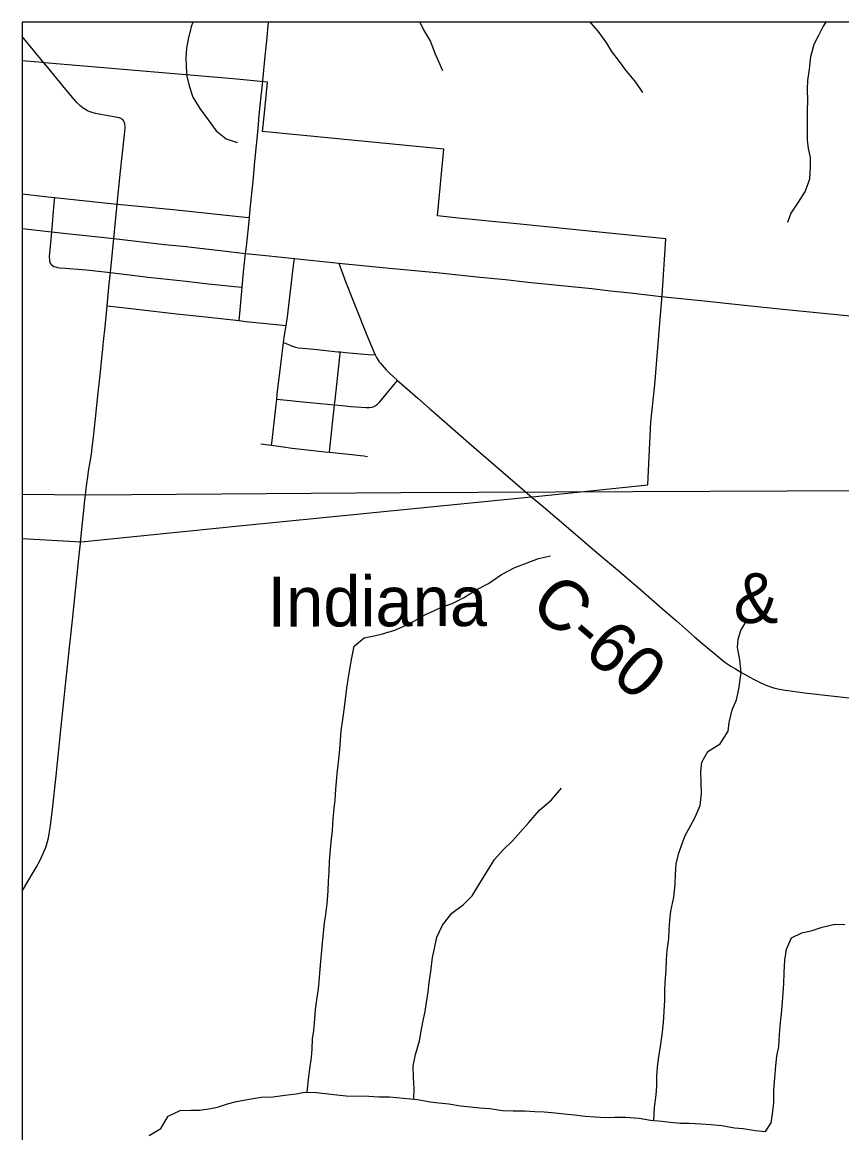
# Model space of a CAD drawing. Extents: x 0 to 1052, y -194 to 246.
# Drawn here: x 1.982 to 2.91, y 19.749 to 21.005 of the extents above; entities that cross this region are included whole.
import ezdxf

# ---------------------------------------------------------------- set-up
doc = ezdxf.new("R2010")
doc.units = 0
for name, color, linetype in [('GM_X_City_Street', 7, 'Continuous'), ('GM_X_Corporation', 7, 'Continuous'), ('GM_X_County_Road', 7, 'Continuous'), ('GM_X_County_Road_Text', 7, 'Continuous'), ('GM_X_Minor_River', 7, 'Continuous'), ('GM_X_Rail_Line', 7, 'Continuous'), ('GM_X_Rail_Line_Text', 7, 'Continuous'), ('GM_X_State_Route', 7, 'Continuous'), ('GM_X_Township_Road', 7, 'Continuous')]:
    doc.layers.add(name, color=color, linetype=linetype)

msp = doc.modelspace()

# ---------------------------------------------------------------- linework, layer by layer
at = {"layer": 'GM_X_City_Street'}
for points in [[(1.9822, 20.8114), (2.008, 20.8085), (2.0186, 20.8073), (2.0437, 20.8045), (2.0897, 20.7995), (2.1022, 20.7984), (2.1529, 20.7936), (2.164, 20.7925), (2.1991, 20.7888), (2.2343, 20.7851), (2.2393, 20.7846)], [(2.0186, 20.8073), (2.018, 20.8008), (2.0152, 20.7685), (2.013, 20.744), (2.0128, 20.7414), (2.0127, 20.7392), (2.0129, 20.7371), (2.0131, 20.7353), (2.0139, 20.7329), (2.0149, 20.7314), (2.0163, 20.7302), (2.0179, 20.7293), (2.0203, 20.7286), (2.0222, 20.7282), (2.0246, 20.7278), (2.0308, 20.7273), (2.05, 20.7259), (2.0549, 20.7253), (2.0753, 20.7232), (2.0819, 20.7223), (2.0851, 20.7219), (2.1097, 20.7188), (2.1245, 20.7171), (2.1678, 20.7124), (2.1801, 20.7109), (2.1893, 20.7098), (2.2004, 20.7087), (2.2224, 20.7065), (2.2312, 20.7057)], [(2.2276, 20.668), (2.2284, 20.6761), (2.2308, 20.7011), (2.2312, 20.7057), (2.2327, 20.7227), (2.2349, 20.744)], [(2.2644, 20.5269), (2.265, 20.5324), (2.2692, 20.5694), (2.2701, 20.5792), (2.2707, 20.5848), (2.275, 20.6212), (2.2779, 20.6431), (2.279, 20.6513), (2.2807, 20.6625), (2.2822, 20.6723), (2.2892, 20.7302), (2.2902, 20.7382)], [(2.0783, 20.6845), (2.0985, 20.6823), (2.131, 20.6787), (2.1569, 20.6758), (2.1791, 20.6734), (2.2069, 20.6705), (2.2276, 20.668), (2.2353, 20.6671), (2.2656, 20.664), (2.2807, 20.6625)], [(2.2779, 20.6431), (2.2853, 20.64), (2.287, 20.6393), (2.2893, 20.6386), (2.2915, 20.6379), (2.2949, 20.6373), (2.2998, 20.6368), (2.3159, 20.6352), (2.3394, 20.6327), (2.3423, 20.6325), (2.3481, 20.632), (2.3736, 20.6298), (2.3817, 20.6291)], [(2.3299, 20.519), (2.3307, 20.5267), (2.3355, 20.5728), (2.3361, 20.578), (2.3417, 20.6275), (2.3423, 20.6325)], [(2.2701, 20.5792), (2.3039, 20.5758), (2.3355, 20.5728), (2.3442, 20.5719), (2.3541, 20.5708), (2.3715, 20.5696), (2.3732, 20.5696), (2.3752, 20.5697), (2.3777, 20.5701), (2.3794, 20.5706), (2.3806, 20.5711), (2.3817, 20.5717), (2.3828, 20.5724), (2.3842, 20.5735), (2.3868, 20.5762), (2.4032, 20.5957), (2.4069, 20.6002)], [(2.2521, 20.5286), (2.2607, 20.5274), (2.2644, 20.5269), (2.2773, 20.525), (2.2876, 20.5237), (2.3013, 20.522), (2.3247, 20.5196), (2.3299, 20.519), (2.355, 20.5164), (2.3648, 20.5153), (2.3688, 20.5149), (2.3728, 20.5141)]]:
    msp.add_lwpolyline(points, dxfattribs=at)
at = {"layer": 'GM_X_Corporation'}
for points in [[(5.1788, 17.6981), (5.491, 17.9457), (6.1888, 18.4644), (6.5994, 18.7694), (6.8785, 18.9763), (8.1871, 19.9814), (8.6571, 20.341), (8.7822, 20.435), (8.7822, 21.0055), (1.9822, 21.0055), (1.9822, 14.2055)], [(5.1788, 17.6981), (5.491, 17.9457), (6.1888, 18.4644), (6.152, 18.6129), (5.992, 19.3448), (5.9283, 19.6076), (5.6935, 20.5776), (5.5898, 21.0055), (1.9822, 21.0055), (1.9822, 14.2055)]]:
    msp.add_lwpolyline(points, dxfattribs=at)
msp.add_lwpolyline([(1.9822, 20.9617), (1.9822, 20.4216), (2.0488, 20.4178), (2.2277, 20.4357), (2.372, 20.45), (2.5543, 20.4682), (2.5596, 20.4685), (2.6902, 20.4821), (2.6935, 20.5535), (2.6981, 20.5952), (2.7035, 20.6649), (2.7061, 20.6962), (2.7103, 20.7605), (2.6198, 20.7695), (2.5793, 20.7736), (2.5343, 20.7781), (2.5135, 20.7802), (2.4988, 20.7816), (2.4758, 20.7839), (2.452, 20.7863), (2.4593, 20.862), (2.2542, 20.8818), (2.2562, 20.9024), (2.2597, 20.9377), (2.2208, 20.9415), (2.0074, 20.9596), (2.0006, 20.9602)], close=True, dxfattribs=at)
at = {"layer": 'GM_X_County_Road'}
for p, q in [((2.0819, 20.7223), (2.0858, 20.7608)), ((2.5593, 20.4679), (2.5693, 20.4594))]:
    msp.add_line(p, q, dxfattribs=at)
for points in [[(2.254, 20.935), (2.2568, 20.9634), (2.2589, 20.9844), (2.261, 21.0055)], [(2.2491, 20.885), (2.2504, 20.9003), (2.2519, 20.9152), (2.254, 20.935)], [(2.2393, 20.7846), (2.2402, 20.794), (2.2433, 20.8256), (2.2455, 20.8479), (2.2491, 20.885)], [(2.2349, 20.744), (2.2358, 20.7519), (2.2382, 20.773), (2.2393, 20.7846)], [(2.3403, 20.7329), (2.3479, 20.7123), (2.3565, 20.6903), (2.3588, 20.6845), (2.3713, 20.6534), (2.3799, 20.6327), (2.3817, 20.6291)], [(2.0783, 20.6845), (2.0806, 20.7097), (2.0819, 20.7223)], [(2.0481, 20.4163), (2.0482, 20.4173), (2.0521, 20.4568), (2.0527, 20.462), (2.0537, 20.4704), (2.0543, 20.4747), (2.055, 20.4807), (2.0557, 20.4863), (2.0563, 20.4908), (2.0573, 20.4977), (2.0587, 20.5061), (2.0604, 20.517), (2.0609, 20.5202), (2.0614, 20.5243), (2.0628, 20.5362), (2.065, 20.5571), (2.0681, 20.5866), (2.0703, 20.6061), (2.0717, 20.6213), (2.0726, 20.6294), (2.0733, 20.6355), (2.0738, 20.6404), (2.0742, 20.6445), (2.076, 20.6609), (2.0775, 20.6764), (2.0783, 20.6845)], [(2.3817, 20.6291), (2.3829, 20.6264), (2.385, 20.6233), (2.3862, 20.6214), (2.3876, 20.6197), (2.3893, 20.6175), (2.3916, 20.6149), (2.3939, 20.6123), (2.3972, 20.609), (2.4018, 20.6048), (2.4069, 20.6002)], [(2.4069, 20.6002), (2.4298, 20.5801), (2.4429, 20.5687), (2.4508, 20.5617), (2.4724, 20.543), (2.4907, 20.527), (2.5509, 20.475), (2.5593, 20.4679)], [(2.5693, 20.4594), (2.6054, 20.4287), (2.6328, 20.4053), (2.6579, 20.384), (2.682, 20.3635), (2.7007, 20.3471), (2.7096, 20.3394), (2.7223, 20.3284), (2.7428, 20.3103), (2.7527, 20.3018), (2.7704, 20.2871), (2.7773, 20.2818), (2.784, 20.2772), (2.7891, 20.2741), (2.7951, 20.2703), (2.7995, 20.2679), (2.8055, 20.2645), (2.8096, 20.2624), (2.8149, 20.2597), (2.8229, 20.2561), (2.8299, 20.2534), (2.8336, 20.2522), (2.839, 20.2511), (2.8455, 20.2501), (2.8514, 20.2492), (2.8674, 20.2471), (2.9008, 20.2433), (2.9384, 20.239)], [(1.9822, 20.0227), (1.9863, 20.0297), (1.998, 20.0495), (2.0025, 20.0576), (2.0041, 20.061), (2.0056, 20.0643), (2.007, 20.0677), (2.0084, 20.0712), (2.0096, 20.0748), (2.0109, 20.0788), (2.0118, 20.083), (2.0128, 20.0872), (2.0136, 20.0922), (2.0143, 20.097), (2.0164, 20.1154), (2.0204, 20.1532), (2.0263, 20.2088), (2.034, 20.2842), (2.039, 20.3293), (2.0462, 20.3991), (2.0481, 20.4163)]]:
    msp.add_lwpolyline(points, dxfattribs=at)
at = {"layer": 'GM_X_Minor_River'}
for points in [[(2.1752, 21.0055), (2.1734, 21.0004), (2.1698, 20.9864), (2.1681, 20.9762), (2.1672, 20.9652), (2.1675, 20.9553), (2.1684, 20.9443), (2.171, 20.9336), (2.1753, 20.9207), (2.1832, 20.908), (2.1925, 20.895), (2.2018, 20.8827), (2.2131, 20.8735), (2.2252, 20.8695)], [(2.4322, 21.0055), (2.4362, 20.997), (2.444, 20.9836), (2.4491, 20.9703), (2.4535, 20.9603), (2.4576, 20.9508)], [(2.6245, 21.0055), (2.625, 21.0048), (2.6336, 20.9952), (2.6433, 20.9818), (2.6489, 20.9722), (2.6575, 20.9611), (2.6646, 20.9512), (2.6762, 20.9377), (2.684, 20.9258)], [(2.8913, 21.0055), (2.8886, 21.001), (2.8831, 20.9905), (2.878, 20.9803), (2.8741, 20.9663), (2.8727, 20.9522), (2.8707, 20.9397), (2.8705, 20.9299), (2.8707, 20.9166), (2.8702, 20.9056), (2.8704, 20.8946), (2.8703, 20.8843), (2.8705, 20.8722), (2.8715, 20.8627), (2.8737, 20.8524), (2.8739, 20.8421), (2.873, 20.8281), (2.8679, 20.8145), (2.8601, 20.8021), (2.852, 20.7893), (2.848, 20.7791)], [(2.3047, 19.7952), (2.306, 19.8097), (2.3077, 19.8215), (2.3094, 19.8344), (2.3103, 19.8439), (2.3108, 19.8556), (2.3121, 19.8651), (2.3134, 19.878), (2.3139, 19.8886), (2.3156, 19.8996), (2.3173, 19.9121), (2.3186, 19.925), (2.3195, 19.939), (2.3218, 19.9637), (2.323, 19.975), (2.3243, 19.9868), (2.3256, 19.9963), (2.3273, 20.0084), (2.3282, 20.0228), (2.3288, 20.0338), (2.3293, 20.0444), (2.3298, 20.0562), (2.3307, 20.0657), (2.3316, 20.0782), (2.3333, 20.0911), (2.3339, 20.1047), (2.3352, 20.1161), (2.3361, 20.1256), (2.337, 20.1381), (2.3387, 20.1552), (2.34, 20.1684), (2.3414, 20.1828), (2.3423, 20.1938), (2.3432, 20.2041), (2.3449, 20.2169), (2.3469, 20.2302), (2.3478, 20.2397), (2.3495, 20.2522), (2.3508, 20.262), (2.3528, 20.2738), (2.3553, 20.2867), (2.3577, 20.2999), (2.3689, 20.3093), (2.3803, 20.3114), (2.3898, 20.3135), (2.4036, 20.3179), (2.4166, 20.3234), (2.4261, 20.3283), (2.4384, 20.3357), (2.4479, 20.3397), (2.4575, 20.3442), (2.4685, 20.3478), (2.4815, 20.3545), (2.4957, 20.3634), (2.5099, 20.3705), (2.5244, 20.3809), (2.5397, 20.3887), (2.5535, 20.3938), (2.5664, 20.399), (2.5798, 20.4018)], [(2.6969, 19.7633), (2.6976, 19.7781), (2.6993, 19.7921), (2.7002, 19.802), (2.7003, 19.813), (2.7009, 19.824), (2.7025, 19.8354), (2.7046, 19.8494), (2.7063, 19.86), (2.7076, 19.874), (2.7085, 19.8865), (2.7091, 19.8994), (2.7092, 19.9097), (2.7097, 19.9192), (2.7107, 19.9332), (2.7112, 19.945), (2.7121, 19.9556), (2.7138, 19.9692), (2.7143, 19.9787), (2.7148, 19.9893), (2.7161, 19.9999), (2.7194, 20.0158), (2.7211, 20.0306), (2.7212, 20.042), (2.7221, 20.0534), (2.7246, 20.0644), (2.7285, 20.0753), (2.7321, 20.0855), (2.7379, 20.0957), (2.7437, 20.1062), (2.7492, 20.1195), (2.7509, 20.1331), (2.7503, 20.1464), (2.7501, 20.1574), (2.751, 20.1684), (2.758, 20.1805), (2.7718, 20.1894), (2.7811, 20.2037), (2.782, 20.2132), (2.7856, 20.2276), (2.7903, 20.2389), (2.7931, 20.251), (2.7957, 20.2699), (2.7943, 20.2844), (2.7915, 20.2981), (2.7924, 20.3076), (2.7952, 20.3174), (2.8029, 20.3302)], [(2.4253, 19.7873), (2.4255, 19.7995), (2.4249, 19.8116), (2.4247, 19.8249), (2.4272, 19.8378), (2.4316, 19.8533), (2.4336, 19.8643), (2.4353, 19.8745), (2.4381, 19.8866), (2.4397, 19.8965), (2.4414, 19.9086), (2.4427, 19.9192), (2.4444, 19.9317), (2.4465, 19.9476), (2.4485, 19.9578), (2.4514, 19.9707), (2.4576, 19.9843), (2.4681, 19.9978), (2.4815, 20.0075), (2.4911, 20.0173), (2.4989, 20.0297), (2.5086, 20.0455), (2.5167, 20.0583), (2.5264, 20.0692), (2.5368, 20.0797), (2.546, 20.0898), (2.5553, 20.1003), (2.5676, 20.1142), (2.581, 20.1258), (2.5922, 20.139)], [(2.8295, 19.7604), (2.8312, 19.7703), (2.8325, 19.7836), (2.8327, 19.7976), (2.8336, 19.8116), (2.835, 19.8249), (2.8359, 19.8359), (2.8383, 19.8469), (2.8389, 19.8605), (2.8402, 19.8742), (2.8414, 19.884), (2.8424, 19.8969), (2.8433, 19.9076), (2.8438, 19.9178), (2.8443, 19.9307), (2.8449, 19.9444), (2.847, 19.9569), (2.8525, 19.9697), (2.8643, 19.9756), (2.8761, 19.9781), (2.8872, 19.9818), (2.9017, 19.9854), (2.913, 19.9849)], [(2.1259, 19.7464), (2.1389, 19.7542), (2.1475, 19.7681), (2.1608, 19.7744), (2.173, 19.775), (2.1829, 19.7749), (2.1935, 19.7763), (2.2031, 19.7784), (2.2145, 19.7821), (2.2248, 19.7846), (2.2389, 19.7875), (2.2526, 19.7896), (2.2663, 19.7901), (2.2792, 19.7919), (2.2921, 19.7932), (2.3017, 19.7954), (2.315, 19.7948), (2.3248, 19.7939), (2.3381, 19.7922), (2.3487, 19.791), (2.3745, 19.7906), (2.3855, 19.7901), (2.3977, 19.79), (2.4136, 19.7886), (2.4296, 19.7869), (2.4436, 19.7844), (2.4534, 19.7832), (2.4648, 19.7819), (2.4781, 19.7798), (2.4895, 19.7785), (2.5001, 19.7776), (2.5111, 19.7767), (2.5255, 19.7746), (2.5376, 19.7741), (2.5509, 19.7743), (2.5623, 19.7734), (2.5729, 19.7729), (2.5851, 19.772), (2.5953, 19.7707), (2.6071, 19.7698), (2.6188, 19.7681), (2.6306, 19.7672), (2.6416, 19.7667), (2.6522, 19.7669), (2.6648, 19.7671), (2.6803, 19.7658), (2.6932, 19.7637), (2.7057, 19.7624), (2.7152, 19.7612), (2.727, 19.7603), (2.7369, 19.7601), (2.7502, 19.7596), (2.7615, 19.7587), (2.7737, 19.7574), (2.7881, 19.7549), (2.7979, 19.754), (2.812, 19.7519), (2.823, 19.7507), (2.8295, 19.7604)]]:
    msp.add_lwpolyline(points, dxfattribs=at)
at = {"layer": 'GM_X_Rail_Line'}
msp.add_lwpolyline([(1.9822, 20.4716), (2.0551, 20.4708), (2.4106, 20.4737), (3.1102, 20.4767), (3.8818, 20.4767), (4.2729, 20.4769), (4.6986, 20.4854), (5.3445, 20.496), (5.674, 20.5018), (6.3876, 20.5117), (6.862, 20.5208), (7.7527, 20.5376), (8.5619, 20.5538), (8.7822, 20.5583)], dxfattribs=at)
at = {"layer": 'GM_X_State_Route'}
for points in [[(1.9822, 20.7723), (1.989, 20.7715), (2.0152, 20.7685), (2.0321, 20.7666)], [(2.0321, 20.7666), (2.047, 20.7649), (2.0858, 20.7608)], [(2.0858, 20.7608), (2.1433, 20.7542), (2.168, 20.7516)], [(2.168, 20.7516), (2.1739, 20.751), (2.2097, 20.7469), (2.2349, 20.744), (2.2616, 20.7413), (2.2902, 20.7382), (2.3403, 20.7329), (2.3977, 20.7272), (2.4511, 20.7222), (2.5005, 20.7172)], [(2.5005, 20.7172), (2.5291, 20.7143), (2.5544, 20.7116), (2.6267, 20.7041), (2.6477, 20.7017), (2.6706, 20.6992), (2.7052, 20.6953)], [(2.7052, 20.6953), (2.7575, 20.69), (2.7958, 20.6858), (2.8465, 20.6806), (2.9188, 20.6733), (2.9942, 20.6654), (3.0479, 20.66), (3.0807, 20.6568), (3.1184, 20.653), (3.126, 20.6523), (3.1605, 20.6487), (3.1852, 20.6461), (3.2594, 20.6386), (3.2873, 20.636), (3.3627, 20.6283), (3.4604, 20.6191), (3.581, 20.6074), (3.6855, 20.5969), (3.7114, 20.5943), (3.7257, 20.5929), (3.7399, 20.5916), (3.7658, 20.5887), (3.785, 20.5872), (3.8061, 20.5854)]]:
    msp.add_lwpolyline(points, dxfattribs=at)
at = {"layer": 'GM_X_Township_Road'}
msp.add_line((2.0858, 20.7608), (2.0897, 20.7995), dxfattribs=at)
for points in [[(2.0068, 20.9594), (1.9947, 20.9743), (1.9822, 20.9894)], [(2.0897, 20.7995), (2.0934, 20.8369), (2.0952, 20.8542), (2.0982, 20.882), (2.0985, 20.8862), (2.0985, 20.8879), (2.0984, 20.8892), (2.0982, 20.8905), (2.098, 20.8915), (2.0974, 20.8931), (2.0965, 20.8945), (2.0954, 20.8956), (2.094, 20.8965), (2.0929, 20.897), (2.0918, 20.8973), (2.0899, 20.8978), (2.0877, 20.8982), (2.0711, 20.9009), (2.065, 20.9022), (2.0624, 20.9028), (2.0601, 20.9037), (2.0581, 20.9045), (2.056, 20.9054), (2.0543, 20.9064), (2.0527, 20.9073), (2.051, 20.9084), (2.0491, 20.9098), (2.0474, 20.9114), (2.0458, 20.9128), (2.0439, 20.9148), (2.0415, 20.9175), (2.0316, 20.9294), (2.0111, 20.9544), (2.0068, 20.9594)]]:
    msp.add_lwpolyline(points, dxfattribs=at)

# ---------------------------------------------------------------- texts
at = {"layer": 'GM_X_County_Road_Text'}
msp.add_text('C-60', height=0.05682, rotation=319.3653, dxfattribs=at).set_placement((2.5543, 20.3432))
at = {"layer": 'GM_X_Rail_Line_Text'}
for s, height, rotation, p in [('Indiana', 0.05663, 0.1716, (2.2598, 20.3218)), ('&', 0.0566, 0, (2.7872, 20.3259))]:
    msp.add_text(s, height=height, rotation=rotation, dxfattribs=at).set_placement(p)

doc.saveas('drawing.dxf')
